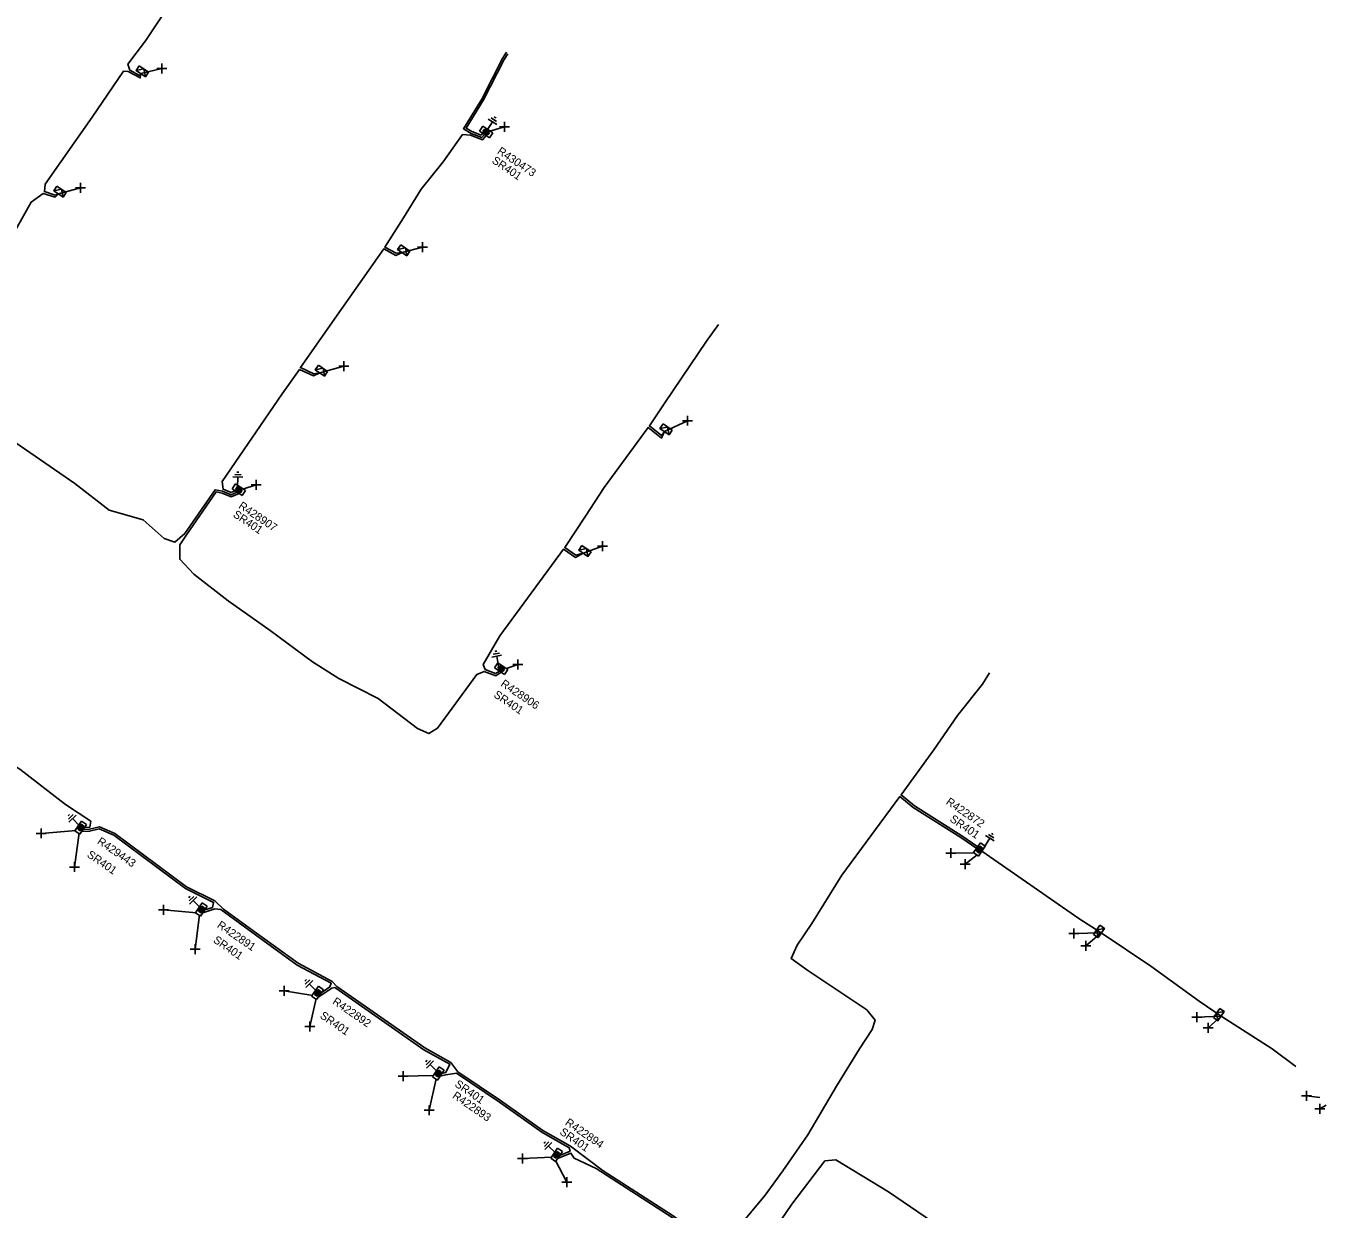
# Model space of a CAD drawing. Extents: x -540247 to -537390, y -1183890 to -1180355.
# Drawn here: x -538895.4 to -538733, y -1181440.1 to -1181292.1 of the extents above; entities that cross this region are included whole.
import ezdxf

# ---------------------------------------------------------------- set-up
doc = ezdxf.new("R2010")
doc.units = 0
for name, color, linetype in [('Vrstva 1', 7, 'Continuous'), ('Vrstva 14', 7, 'Continuous'), ('Vrstva 15', 7, 'Continuous'), ('Vrstva 28', 7, 'Continuous'), ('Vrstva 29', 7, 'Continuous'), ('Vrstva 30', 7, 'Continuous'), ('Vrstva 31', 7, 'Continuous'), ('Vrstva 34', 7, 'Continuous'), ('Vrstva 5', 7, 'Continuous'), ('Vrstva 59', 7, 'Continuous'), ('Vrstva 8', 7, 'Continuous'), ('Vrstva 9', 7, 'Continuous')]:
    doc.layers.add(name, color=color, linetype=linetype)

# ---------------------------------------------------------------- blocks, each defined once
blk = doc.blocks.new('NN800')
at = {"layer": 'Vrstva 1'}
for points in [[(-0.44, 0.44), (0.44, -0.44)], [(-0.44, -0.44), (0.44, 0.44)]]:
    blk.add_lwpolyline(points, dxfattribs=at)
blk = doc.blocks.new('NN620')
at = {"layer": 'Vrstva 8'}
for points in [[(0.75, 0), (-0.75, 0)], [(-0.75, 0), (-0.75, -0.75)], [(0.75, -0.75), (0.75, 0)], [(-0.75, -0.75), (0.75, -0.75)], [(0.37, -0.18), (-0.38, -0.18)], [(-0.38, -0.18), (-0.38, -0.56)], [(-0.38, -0.56), (0.37, -0.56)], [(0.32, -0.23), (-0.33, -0.23)], [(-0.33, -0.23), (-0.33, -0.51)], [(-0.33, -0.51), (0.32, -0.51)], [(0.27, -0.27), (-0.28, -0.27)], [(-0.28, -0.27), (-0.28, -0.46)], [(-0.28, -0.46), (0.27, -0.46)], [(0.23, -0.32), (-0.23, -0.32)], [(-0.23, -0.32), (-0.23, -0.42)], [(-0.23, -0.42), (0.23, -0.42)], [(-0.19, -0.37), (0.19, -0.37)], [(0.23, -0.42), (0.23, -0.32)], [(0.27, -0.46), (0.27, -0.27)], [(0.32, -0.51), (0.32, -0.23)], [(0.37, -0.56), (0.37, -0.18)]]:
    blk.add_lwpolyline(points, dxfattribs=at)
blk = doc.blocks.new('NN630')
at = {"layer": 'Vrstva 9'}
for points in [[(0, -0.7), (-0.7, 0)], [(-0.7, -0.7), (-0.7, 0), (0.7, 0), (0.7, -0.7)], [(-0.7, -0.7), (0.7, -0.7)], [(0, -0.7), (0.7, 0)]]:
    blk.add_lwpolyline(points, dxfattribs=at)
blk = doc.blocks.new('NN810')
at = {"layer": 'Vrstva 14'}
for points in [[(0, -0.64), (0, -1.89)], [(0.63, -1.89), (-0.62, -1.89)], [(0.39, -2.2), (-0.4, -2.2)], [(0, -2.52), (-0.12, -2.52)], [(0.14, -2.52), (0, -2.52)]]:
    blk.add_lwpolyline(points, dxfattribs=at)

msp = doc.modelspace()

# ---------------------------------------------------------------- linework, layer by layer
at = {"layer": 'Vrstva 5'}
for points in [[(-538876.6, -1181288.05), (-538880.49, -1181293.95), (-538882.71, -1181296.89), (-538882.46, -1181297.61), (-538881.24, -1181298.27), (-538881.1, -1181298.04), (-538881.16, -1181298.59), (-538882.67, -1181297.78), (-538883.26, -1181297.76), (-538887.18, -1181303.5), (-538893.05, -1181311.89), (-538893.15, -1181312.81), (-538891.79, -1181313.26), (-538891.39, -1181313.1), (-538891.78, -1181313.52), (-538893.29, -1181313.03), (-538894.78, -1181314.11), (-538897.72, -1181319.32), (-538903.63, -1181327.31), (-538902.07, -1181328.17), (-538901.52, -1181328.1)], [(-538835.38, -1181295.37), (-538835.9, -1181296.15), (-538838.48, -1181301.23), (-538840.77, -1181304.94), (-538839.79, -1181305.53), (-538838.47, -1181306.05), (-538838.15, -1181305.66)], [(-538838.35, -1181305.52), (-538838.55, -1181305.75), (-538839.7, -1181305.3), (-538840.43, -1181304.88), (-538838.26, -1181301.35), (-538835.68, -1181296.27), (-538835.22, -1181295.58)], [(-538869.29, -1181350.24), (-538869.79, -1181350.46), (-538870.8, -1181350.03), (-538870.93, -1181349.05), (-538863.41, -1181338.11), (-538861.25, -1181335.04), (-538859.51, -1181335.84), (-538858.71, -1181335.48), (-538859.47, -1181335.58), (-538861.15, -1181334.82), (-538856.05, -1181327.55), (-538850.73, -1181319.97), (-538849.23, -1181320.78), (-538848.42, -1181320.43), (-538849.19, -1181320.52), (-538850.61, -1181319.75), (-538848.26, -1181316.09), (-538846.03, -1181312.52), (-538843.29, -1181309.09), (-538840.88, -1181305.65), (-538839.88, -1181305.76), (-538838.39, -1181306.35), (-538837.94, -1181305.8)], [(-538901.35, -1181328.21), (-538902.12, -1181328.43), (-538903.82, -1181327.49), (-538904.61, -1181328.02), (-538908.52, -1181333.8), (-538908.51, -1181335.18), (-538907.95, -1181336.57), (-538905.78, -1181338.37), (-538896.83, -1181344.13), (-538889.35, -1181349.32), (-538885.03, -1181352.64), (-538880.81, -1181353.87), (-538878.18, -1181356.19), (-538876.84, -1181356.64), (-538875.59, -1181355.58), (-538871.8, -1181350.1), (-538870.87, -1181350.27), (-538869.79, -1181350.73), (-538869.04, -1181350.41)], [(-538836.26, -1181372.77), (-538836.75, -1181373.09), (-538838.07, -1181372.58), (-538838.3, -1181371.97), (-538836.21, -1181368.35), (-538828.25, -1181357.52), (-538826.76, -1181358.56), (-538825.78, -1181358.03), (-538826.72, -1181358.28), (-538828.11, -1181357.32), (-538825.51, -1181353.41), (-538823.16, -1181349.81), (-538817.69, -1181342.32), (-538815.99, -1181343.64), (-538815.64, -1181342.83), (-538816.03, -1181343.3), (-538817.53, -1181342.12), (-538815.59, -1181339.23), (-538810.4, -1181331.51), (-538808.89, -1181329.43)], [(-538868.8, -1181350.57), (-538869.79, -1181351), (-538870.94, -1181350.51), (-538871.68, -1181350.36), (-538875.39, -1181355.72), (-538876.22, -1181356.99), (-538876.23, -1181358.78), (-538874.47, -1181360.64), (-538870.18, -1181364), (-538864.91, -1181367.69), (-538859.62, -1181371.6), (-538856.32, -1181373.72), (-538851.43, -1181376.22), (-538846.49, -1181379.96), (-538845.08, -1181380.59), (-538844.02, -1181379.92), (-538839.1, -1181373.21), (-538838.17, -1181372.82), (-538836.71, -1181373.37), (-538836.04, -1181372.92)], [(-538776.49, -1181394.76), (-538778.46, -1181393.38), (-538784.4, -1181389.62), (-538786.06, -1181388.27), (-538781.95, -1181382.62), (-538779.01, -1181378.34), (-538775.9, -1181374.42), (-538775.02, -1181372.98)], [(-538903.23, -1181382.58), (-538902.08, -1181382.3), (-538900.71, -1181382.36), (-538896.23, -1181385.05), (-538890.51, -1181389.46), (-538887.34, -1181391.55), (-538887.48, -1181392.31), (-538888.12, -1181392.32)], [(-538807.98, -1181451.14), (-538805.49, -1181448.44), (-538805.07, -1181446.97), (-538807.96, -1181444.03), (-538806.36, -1181442.28), (-538803.07, -1181438.32), (-538800.84, -1181435.28), (-538797.72, -1181430.79), (-538794.12, -1181424.69), (-538791.28, -1181420.03), (-538789.66, -1181417.6), (-538789.3, -1181416.42), (-538790.35, -1181415.15), (-538797.73, -1181410.23), (-538799.81, -1181408.71), (-538799.06, -1181407.05), (-538797.2, -1181404.36), (-538793.47, -1181398.28), (-538786.22, -1181388.48), (-538784.54, -1181389.82), (-538778.6, -1181393.59), (-538776.61, -1181394.98)], [(-538888.47, -1181392.83), (-538887.49, -1181392.8), (-538886.28, -1181392.5), (-538884.46, -1181393.31), (-538875.5, -1181399.98), (-538871.99, -1181401.71), (-538872.11, -1181402.33), (-538873.09, -1181402.65)], [(-538888.29, -1181392.57), (-538887.52, -1181392.55), (-538886.24, -1181392.24), (-538884.34, -1181393.09), (-538875.36, -1181399.76), (-538871.83, -1181401.51), (-538870.75, -1181402.54), (-538866.63, -1181405.56), (-538861.42, -1181409.32), (-538857.16, -1181411.59), (-538856.57, -1181412.23), (-538845.58, -1181419.91), (-538842.35, -1181421.71), (-538841.45, -1181422.89), (-538836.12, -1181426.5), (-538830.84, -1181430.24), (-538827.39, -1181432.21), (-538823.29, -1181435.26), (-538814.54, -1181440.92), (-538810.94, -1181443.6), (-538808.43, -1181445.64), (-538805.35, -1181447.04), (-538805.71, -1181448.31), (-538808.19, -1181451)], [(-538736.71, -1181422.24), (-538739.67, -1181420), (-538746.06, -1181415.93), (-538748.8, -1181414.05), (-538754.84, -1181409.68), (-538761.04, -1181405.53), (-538763.85, -1181403.72), (-538775.96, -1181395.29)], [(-538873.32, -1181403), (-538871.84, -1181402.51), (-538871.09, -1181402.6), (-538866.77, -1181405.76), (-538861.56, -1181409.54), (-538857.29, -1181411.81), (-538857.46, -1181412.28), (-538858.47, -1181412.96)], [(-538858.86, -1181413.52), (-538857.23, -1181412.42), (-538856.83, -1181412.35), (-538856.73, -1181412.42), (-538845.72, -1181420.13), (-538842.48, -1181421.93), (-538842.95, -1181423), (-538843.46, -1181423.11)], [(-538843.67, -1181423.42), (-538842.98, -1181423.26), (-538841.64, -1181423.06), (-538841.63, -1181423.07), (-538836.26, -1181426.7), (-538830.98, -1181430.46), (-538827.56, -1181432.39), (-538827.44, -1181432.83), (-538828.65, -1181433.31)], [(-538828.9, -1181433.68), (-538827.34, -1181433.06), (-538826.94, -1181433.71), (-538824.16, -1181434.99), (-538814.68, -1181441.12), (-538811.1, -1181443.8), (-538808.55, -1181445.86), (-538805.65, -1181447.19), (-538805.94, -1181448.19), (-538808.39, -1181450.85)], [(-538804.79, -1181446.9), (-538799.71, -1181439.45), (-538795.58, -1181434.02), (-538794.22, -1181433.91), (-538787.64, -1181437.92), (-538777.57, -1181444.8)]]:
    msp.add_lwpolyline(points, dxfattribs=at)
at = {"layer": 'Vrstva 59'}
for points in [[(-538881.1, -1181298.04), (-538878.45, -1181297.4)], [(-538837.47, -1181305.27), (-538835.65, -1181304.71)], [(-538891.39, -1181313.1), (-538888.64, -1181312.35)], [(-538848.42, -1181320.43), (-538845.87, -1181319.74)], [(-538858.71, -1181335.48), (-538855.72, -1181334.63)], [(-538815.64, -1181342.83), (-538812.77, -1181341.46)], [(-538868.32, -1181350.02), (-538866.67, -1181349.48)], [(-538825.78, -1181358.03), (-538823.38, -1181357.15)], [(-538835.4, -1181372.47), (-538833.97, -1181371.97)], [(-538889.19, -1181392.72), (-538893.54, -1181393.07)], [(-538888.78, -1181393.02), (-538889.39, -1181397.28)], [(-538776.9, -1181395.51), (-538779.86, -1181395.53)], [(-538776.57, -1181395.77), (-538778.06, -1181396.91)], [(-538874.15, -1181403), (-538878.26, -1181402.64)], [(-538873.76, -1181403.25), (-538874.3, -1181407.54)], [(-538761.04, -1181405.53), (-538764.47, -1181405.58)], [(-538761.04, -1181405.53), (-538762.98, -1181407.15)], [(-538859.61, -1181413.36), (-538863.19, -1181412.75)], [(-538859.19, -1181413.73), (-538859.98, -1181417.22)], [(-538746.06, -1181415.93), (-538749.11, -1181416.05)], [(-538746.06, -1181415.93), (-538747.68, -1181417.41)], [(-538844.53, -1181423.37), (-538848.31, -1181423.43)], [(-538844.18, -1181423.76), (-538845.06, -1181427.71)], [(-538733.72, -1181426.09), (-538735.39, -1181425.91)], [(-538732.95, -1181427.07), (-538733.72, -1181427.53)], [(-538829.73, -1181433.56), (-538833.39, -1181433.73)], [(-538829.26, -1181433.99), (-538827.84, -1181436.69)]]:
    msp.add_lwpolyline(points, dxfattribs=at)

# ---------------------------------------------------------------- block references
at = {"layer": 'Vrstva 15'}
for p, rotation in [((-538838.15, -1181305.66), 147.3554277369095), ((-538869.04, -1181350.41), 177.9955499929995), ((-538836.26, -1181372.77), -169.66730003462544), ((-538888.29, -1181392.57), -135), ((-538775.96, -1181395.29), 148.46816385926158), ((-538873.21, -1181402.8), -135), ((-538858.7, -1181413.23), -135), ((-538843.6, -1181423.31), -135), ((-538828.82, -1181433.5), -134.99999990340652)]:
    msp.add_blockref('NN810', p, dxfattribs=dict(at, rotation=rotation))
at = {"layer": 'Vrstva 28'}
for p, rotation in [((-538838.15, -1181305.66), 145.96776391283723), ((-538869.04, -1181350.41), 145.96776383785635), ((-538836.26, -1181372.77), 145.96776391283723), ((-538888.29, -1181392.57), -124.4581195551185), ((-538775.96, -1181395.29), -124.37427226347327), ((-538873.21, -1181402.8), -124.45811942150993), ((-538858.7, -1181413.24), -124.45811942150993), ((-538843.6, -1181423.31), -124.45811942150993), ((-538828.82, -1181433.5), -124.45811942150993)]:
    msp.add_blockref('NN620', p, dxfattribs=dict(at, rotation=rotation))
at = {"layer": 'Vrstva 31'}
for p, rotation in [((-538881.1, -1181298.04), 145.4969610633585), ((-538891.39, -1181313.1), 145.4969610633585), ((-538848.42, -1181320.43), 145.49696095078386), ((-538858.71, -1181335.48), 145.4969610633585), ((-538815.64, -1181342.83), 145.4969610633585), ((-538825.78, -1181358.03), 145.4969610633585), ((-538761.04, -1181405.53), -124.44761382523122), ((-538746.06, -1181415.93), -124.43898898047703)]:
    msp.add_blockref('NN630', p, dxfattribs=dict(at, rotation=rotation))
at = {"layer": 'Vrstva 34'}
for p, rotation in [((-538878.45, -1181297.4), 45), ((-538835.65, -1181304.71), 45), ((-538888.64, -1181312.35), 45), ((-538845.87, -1181319.74), 45), ((-538855.72, -1181334.63), 45), ((-538812.77, -1181341.46), 44.99999995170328), ((-538866.67, -1181349.48), 45), ((-538823.38, -1181357.15), 45), ((-538833.97, -1181371.97), 44.99999995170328), ((-538893.54, -1181393.07), 44.99999995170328), ((-538779.86, -1181395.53), 44.99999995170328), ((-538889.39, -1181397.28), 45), ((-538778.06, -1181396.91), 45), ((-538878.26, -1181402.64), 45.00000009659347), ((-538764.47, -1181405.58), 45), ((-538874.3, -1181407.54), 45), ((-538762.98, -1181407.15), 45), ((-538863.19, -1181412.75), 45), ((-538859.98, -1181417.22), 45), ((-538749.11, -1181416.06), 45), ((-538747.68, -1181417.41), 44.99999995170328), ((-538848.31, -1181423.43), 45), ((-538735.39, -1181425.91), 45), ((-538845.06, -1181427.71), 45), ((-538733.72, -1181427.53), -45), ((-538833.39, -1181433.73), 45), ((-538827.84, -1181436.69), 45)]:
    msp.add_blockref('NN800', p, dxfattribs=dict(at, rotation=rotation))

# ---------------------------------------------------------------- texts
at = {"layer": 'Vrstva 29'}
for s, rotation, p in [('R430473', 325.968, (-538836.62, -1181307.97)), ('R428907', 325.968, (-538868.97, -1181352.33)), ('R428906', 325.968, (-538836.2, -1181374.58)), ('R422872', 325.626, (-538780.54, -1181389.34)), ('R429443', 325.542, (-538886.63, -1181394.29)), ('R422891', 325.542, (-538871.64, -1181404.76)), ('R422892', 325.542, (-538857.23, -1181414.32)), ('R422893', 325.542, (-538842.23, -1181426.1)), ('R422894', 325.542, (-538828.14, -1181429.45))]:
    msp.add_text(s, height=1, rotation=rotation, dxfattribs=at).set_placement(p)
at = {"layer": 'Vrstva 30'}
for rotation, p in [(325.968, (-538837.3, -1181309.14)), (325.968, (-538869.66, -1181353.4)), (325.968, (-538837.08, -1181375.95)), (325.626, (-538780.06, -1181391.49)), (325.542, (-538887.9, -1181395.95)), (325.542, (-538872.13, -1181406.62)), (325.542, (-538858.79, -1181416.08)), (325.542, (-538841.94, -1181424.64)), (325.542, (-538828.82, -1181430.63))]:
    msp.add_text('SR401', height=1, rotation=rotation, dxfattribs=at).set_placement(p)

doc.saveas('drawing.dxf')
